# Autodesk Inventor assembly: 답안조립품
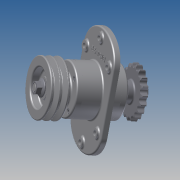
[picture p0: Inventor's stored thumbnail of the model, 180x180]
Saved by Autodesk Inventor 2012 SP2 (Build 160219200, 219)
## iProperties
Created: 2015-02
Part Number: 답안조립품
Document SubType Name: Assembly
Designer: Administrator
Author: Administrator
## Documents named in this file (11)
- C:\Users\Administrator\Desktop\450208V1003\450208V1003\답안조립품.iam
- C:\Users\Administrator\Desktop\450208V1003\450208V1003\본체-1.ipt
- C:\Users\Administrator\Desktop\450208V1003\450208V1003\3-축.ipt
- C:\Users\Administrator\Desktop\450208V1003\450208V1003\6-베어링 6206.ipt
- C:\Users\Administrator\Desktop\450208V1003\450208V1003\2-커버.ipt
- C:\Users\Administrator\Desktop\450208V1003\450208V1003\8-오일실 30x42.ipt
- C:\Users\Administrator\Desktop\450208V1003\450208V1003\11-키 6x6.ipt
- C:\Users\Administrator\Desktop\450208V1003\450208V1003\4-V벨트풀리.ipt
- C:\Users\Administrator\Desktop\450208V1003\450208V1003\5-체인 스프로킷.ipt
- C:\Users\Administrator\Desktop\450208V1003\450208V1003\9-M16-너트.ipt
- C:\Users\Administrator\Desktop\450208V1003\450208V1003\10-M6.ipt
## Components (21 placed, 9 different names)
1. 3-축:1
2. 6-베어링 6206:1
3. 6-베어링 6206:2
4. 2-커버:1
5. 2-커버:2
6. 8-8-오일실 30x42:1
7. 8-8-오일실 30x42:2
8. 11-키 6x6:1
9. 11-키 6x6:2
10. 4-V벨트풀리:1
11. 5-체인 스프로킷:1
12. 9-M16 너트:1
13. 9-M16 너트:2
14. 10-M6:2
15. 10-M6:3
16. 10-M6:4
17. 10-M6:5
18. 10-M6:1
19. 10-M6:6
20. 10-M6:7
21. 10-M6:8
